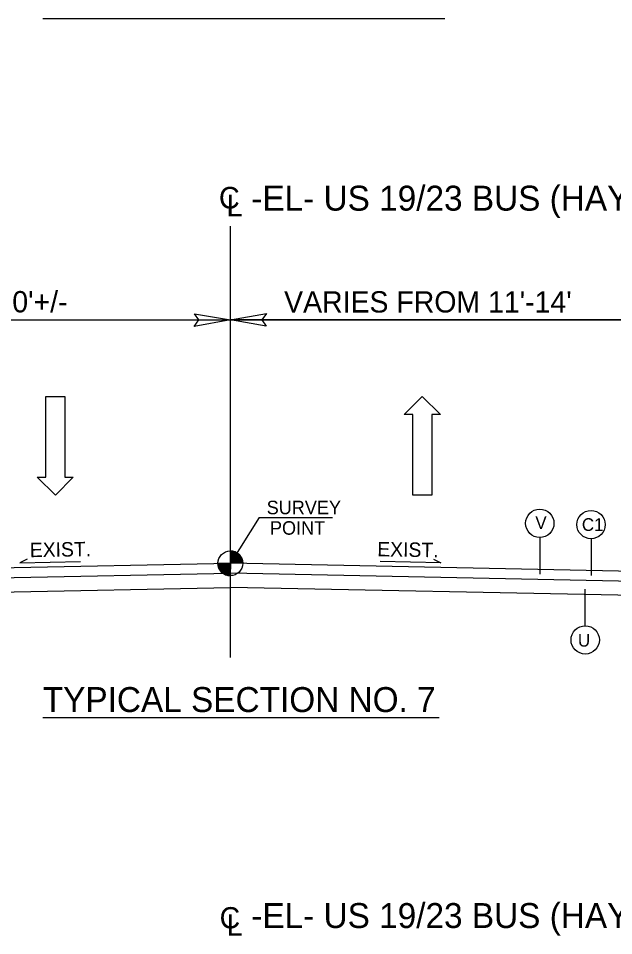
# Model space of a CAD drawing. Extents: x 1022283 to 1026986, y 174822 to 180471.
# Drawn here: x 1023671 to 1024119, y 176179 to 176868 of the extents above; entities that cross this region are included whole.
import ezdxf

# ---------------------------------------------------------------- set-up
doc = ezdxf.new("R2010")
doc.units = 0
for name, color, linetype in [('Default', 7, 'Continuous'), ('Prop Dimension', 7, 'Continuous'), ('Prop Lane Arrow CELL', 7, 'Continuous'), ('Prop Terminator CELL', 7, 'Continuous'), ('Typical Berm Information CELL', 7, 'Continuous'), ('Typical Grade Point Symbol CELL', 7, 'Continuous'), ('Typical ID Circle CELL', 7, 'Continuous'), ('Typical Text Centerline CELL', 7, 'Continuous'), ('Typical Text Grade Point CELL', 7, 'Continuous'), ('Typical Text ID Circle CELL', 7, 'Continuous'), ('Typical Text Label CELL', 7, 'Continuous')]:
    doc.layers.add(name, color=color, linetype=linetype)

# ---------------------------------------------------------------- blocks, each defined once
blk = doc.blocks.new('Lane Arrow Through')
at = {"layer": 'Prop Lane Arrow CELL'}
for p, q in [((-17.15, 1.6), (-3.15, 1.6)), ((-17.15, -1.7), (-17.15, 1.6)), ((-3.15, 1.6), (-3.15, 3.1)), ((-3.15, 3.1), (0, 0)), ((0, 0), (-3.15, -3.2)), ((-3.15, -1.7), (-17.15, -1.7)), ((-3.15, -3.2), (-3.15, -1.7))]:
    blk.add_line(p, q, dxfattribs=at)

msp = doc.modelspace()

# ---------------------------------------------------------------- linework, layer by layer
at = {"layer": 'Default'}
for p, q in [((1023322.83, 176641.78), (1023830.54, 176641.78)), ((1023830.54, 176641.78), (1024338.25, 176641.78)), ((1024338.25, 176641.78), (1023830.54, 176641.78))]:
    msp.add_line(p, q, dxfattribs=at)
at = {"layer": 'Prop Dimension'}
for p, q in [((1023830.54, 176652.9), (1023830.54, 176712.35)), ((1023830.54, 176388.1), (1023830.54, 176652.9)), ((1023852.19, 176493.32), (1023830.54, 176458.89)), ((1023852.19, 176493.32), (1023830.54, 176458.89)), ((1023322.83, 176448.73), (1023830.54, 176458.89)), ((1023322.83, 176448.73), (1023830.54, 176458.89)), ((1024338.25, 176448.73), (1023830.54, 176458.89)), ((1024338.25, 176448.73), (1023830.54, 176458.89)), ((1023322.83, 176441.23), (1023830.54, 176451.38)), ((1023322.83, 176441.23), (1023830.54, 176451.38)), ((1024338.25, 176441.23), (1023830.54, 176451.38)), ((1024338.25, 176441.23), (1023830.54, 176451.38)), ((1023322.83, 176430.65), (1023830.54, 176440.8)), ((1024338.25, 176430.65), (1023830.54, 176440.8))]:
    msp.add_line(p, q, dxfattribs=at)
at = {"layer": 'Prop Terminator CELL'}
for points in [[(1023803.54, 176646.43), (1023830.54, 176641.78), (1023803.39, 176636.98), (1023806.84, 176641.78)], [(1023857.54, 176637.13), (1023830.54, 176641.78), (1023857.69, 176646.58), (1023854.24, 176641.78)], [(1023857.54, 176637.13), (1023830.54, 176641.78), (1023857.69, 176646.58), (1023854.24, 176641.78)]]:
    msp.add_lwpolyline(points, close=True, dxfattribs=at)
at = {"layer": 'Typical Berm Information CELL'}
for p, q in [((1023677.89, 176462.1), (1023672.37, 176459.33)), ((1023672.37, 176459.33), (1023717.88, 176460.24)), ((1023988.71, 176459.33), (1023943.2, 176460.24)), ((1023983.19, 176462.1), (1023988.71, 176459.33))]:
    msp.add_line(p, q, dxfattribs=at)
at = {"layer": 'Typical Grade Point Symbol CELL'}
for p, q in [((1023830.54, 176458.89), (1023830.54, 176468.18)), ((1023830.54, 176458.89), (1023830.54, 176468.18)), ((1023821.24, 176458.89), (1023830.54, 176458.89)), ((1023821.24, 176458.89), (1023830.54, 176458.89)), ((1023830.52, 176449.59), (1023830.54, 176458.89)), ((1023830.54, 176458.89), (1023830.52, 176449.59)), ((1023830.52, 176449.59), (1023830.54, 176458.89)), ((1023830.54, 176458.89), (1023830.52, 176449.59)), ((1023839.83, 176458.89), (1023830.54, 176458.89)), ((1023839.83, 176458.89), (1023830.54, 176458.89))]:
    msp.add_line(p, q, dxfattribs=at)
for points in [[(1023830.62, 176468.18), (1023830.62, 176468.18), (1023830.62, 176458.89)], [(1023830.62, 176468.18), (1023830.62, 176468.18), (1023830.62, 176458.89)], [(1023830.81, 176468.18), (1023830.81, 176458.89)], [(1023830.81, 176468.18), (1023830.81, 176458.89)], [(1023830.99, 176468.16), (1023830.99, 176458.89)], [(1023830.99, 176468.16), (1023830.99, 176458.89)], [(1023831.18, 176468.16), (1023831.18, 176458.89)], [(1023831.18, 176468.16), (1023831.18, 176458.89)], [(1023831.37, 176468.14), (1023831.37, 176458.89)], [(1023831.37, 176468.14), (1023831.37, 176458.89)], [(1023831.55, 176468.12), (1023831.55, 176458.89)], [(1023831.55, 176468.12), (1023831.55, 176458.89)], [(1023831.74, 176468.1), (1023831.74, 176458.89)], [(1023831.74, 176468.1), (1023831.74, 176458.89)], [(1023831.92, 176468.08), (1023831.92, 176458.89)], [(1023831.92, 176468.08), (1023831.92, 176458.89)], [(1023832.11, 176468.06), (1023832.11, 176458.89)], [(1023832.11, 176468.06), (1023832.11, 176458.89)], [(1023832.3, 176468.02), (1023832.3, 176458.89)], [(1023832.3, 176468.02), (1023832.3, 176458.89)], [(1023832.48, 176467.98), (1023832.48, 176458.89)], [(1023832.48, 176467.98), (1023832.48, 176458.89)], [(1023832.67, 176467.93), (1023832.67, 176458.89)], [(1023832.67, 176467.93), (1023832.67, 176458.89)], [(1023832.85, 176467.89), (1023832.85, 176458.89)], [(1023832.85, 176467.89), (1023832.85, 176458.89)], [(1023833.04, 176467.83), (1023833.04, 176458.89)], [(1023833.04, 176467.83), (1023833.04, 176458.89)], [(1023833.22, 176467.79), (1023833.22, 176458.89)], [(1023833.22, 176467.79), (1023833.22, 176458.89)], [(1023833.41, 176467.73), (1023833.41, 176458.89)], [(1023833.41, 176467.73), (1023833.41, 176458.89)], [(1023833.6, 176467.67), (1023833.6, 176458.89)], [(1023833.6, 176467.67), (1023833.6, 176458.89)], [(1023833.78, 176467.6), (1023833.78, 176458.89)], [(1023833.78, 176467.6), (1023833.78, 176458.89)], [(1023833.97, 176467.52), (1023833.97, 176458.89)], [(1023833.97, 176467.52), (1023833.97, 176458.89)], [(1023834.15, 176467.44), (1023834.15, 176458.89)], [(1023834.15, 176467.44), (1023834.15, 176458.89)], [(1023834.34, 176467.36), (1023834.34, 176458.89)], [(1023834.34, 176467.36), (1023834.34, 176458.89)], [(1023834.53, 176467.27), (1023834.53, 176458.89)], [(1023834.53, 176467.27), (1023834.53, 176458.89)], [(1023834.71, 176467.19), (1023834.71, 176458.89)], [(1023834.71, 176467.19), (1023834.71, 176458.89)], [(1023834.9, 176467.09), (1023834.9, 176458.89)], [(1023834.9, 176467.09), (1023834.9, 176458.89)], [(1023835.08, 176466.98), (1023835.08, 176458.89)], [(1023835.08, 176466.98), (1023835.08, 176458.89)], [(1023835.27, 176466.88), (1023835.27, 176458.89)], [(1023835.27, 176466.88), (1023835.27, 176458.89)], [(1023835.46, 176466.78), (1023835.46, 176458.89)], [(1023835.46, 176466.78), (1023835.46, 176458.89)], [(1023835.64, 176466.65), (1023835.64, 176458.89)], [(1023835.64, 176466.65), (1023835.64, 176458.89)], [(1023835.83, 176466.53), (1023835.83, 176458.89)], [(1023835.83, 176466.53), (1023835.83, 176458.89)], [(1023836.01, 176466.39), (1023836.01, 176458.89)], [(1023836.01, 176466.39), (1023836.01, 176458.89)], [(1023836.2, 176466.26), (1023836.2, 176458.89)], [(1023836.2, 176466.26), (1023836.2, 176458.89)], [(1023836.39, 176466.12), (1023836.39, 176458.89)], [(1023836.39, 176466.12), (1023836.39, 176458.89)], [(1023836.57, 176465.95), (1023836.57, 176458.89)], [(1023836.57, 176465.95), (1023836.57, 176458.89)], [(1023836.76, 176465.79), (1023836.76, 176458.89)], [(1023836.76, 176465.79), (1023836.76, 176458.89)], [(1023836.94, 176465.62), (1023836.94, 176458.89)], [(1023836.94, 176465.62), (1023836.94, 176458.89)], [(1023837.13, 176465.43), (1023837.13, 176458.89)], [(1023837.13, 176465.43), (1023837.13, 176458.89)], [(1023837.32, 176465.25), (1023837.32, 176458.89)], [(1023837.32, 176465.25), (1023837.32, 176458.89)], [(1023837.5, 176465.04), (1023837.5, 176458.89)], [(1023837.5, 176465.04), (1023837.5, 176458.89)], [(1023837.69, 176464.82), (1023837.69, 176458.89)], [(1023837.69, 176464.82), (1023837.69, 176458.89)], [(1023837.87, 176464.59), (1023837.87, 176458.89)], [(1023837.87, 176464.59), (1023837.87, 176458.89)], [(1023838.06, 176464.34), (1023838.06, 176458.89)], [(1023838.06, 176464.34), (1023838.06, 176458.89)], [(1023838.25, 176464.07), (1023838.25, 176458.89)], [(1023838.25, 176464.07), (1023838.25, 176458.89)], [(1023838.43, 176463.78), (1023838.43, 176458.89)], [(1023838.43, 176463.78), (1023838.43, 176458.89)], [(1023838.62, 176463.47), (1023838.62, 176458.89)], [(1023838.62, 176463.47), (1023838.62, 176458.89)], [(1023838.8, 176463.14), (1023838.8, 176458.89)], [(1023838.8, 176463.14), (1023838.8, 176458.89)], [(1023838.99, 176462.75), (1023838.99, 176458.89)], [(1023838.99, 176462.75), (1023838.99, 176458.89)], [(1023839.17, 176462.32), (1023839.17, 176458.89)], [(1023839.17, 176462.32), (1023839.17, 176458.89)], [(1023839.36, 176461.8), (1023839.36, 176458.89)], [(1023839.36, 176461.8), (1023839.36, 176458.89)], [(1023839.55, 176461.16), (1023839.55, 176458.89)], [(1023839.55, 176461.16), (1023839.55, 176458.89)], [(1023839.73, 176460.21), (1023839.73, 176458.89)], [(1023839.73, 176460.21), (1023839.73, 176458.89)], [(1023821.29, 176458.89), (1023821.29, 176457.87)], [(1023821.29, 176458.89), (1023821.29, 176457.87)], [(1023821.47, 176458.89), (1023821.47, 176456.78)], [(1023821.47, 176458.89), (1023821.47, 176456.78)], [(1023821.66, 176458.89), (1023821.66, 176456.12)], [(1023821.66, 176458.89), (1023821.66, 176456.12)], [(1023821.84, 176458.89), (1023821.84, 176455.56)], [(1023821.84, 176458.89), (1023821.84, 176455.56)], [(1023822.03, 176458.89), (1023822.03, 176455.13)], [(1023822.03, 176458.89), (1023822.03, 176455.13)], [(1023822.22, 176458.89), (1023822.22, 176454.73)], [(1023822.22, 176458.89), (1023822.22, 176454.73)], [(1023822.4, 176458.89), (1023822.4, 176454.38)], [(1023822.4, 176458.89), (1023822.4, 176454.38)], [(1023822.59, 176458.89), (1023822.59, 176454.05)], [(1023822.59, 176458.89), (1023822.59, 176454.05)], [(1023822.77, 176458.89), (1023822.77, 176453.76)], [(1023822.77, 176458.89), (1023822.77, 176453.76)], [(1023822.96, 176458.89), (1023822.96, 176453.5)], [(1023822.96, 176458.89), (1023822.96, 176453.5)], [(1023823.15, 176458.89), (1023823.15, 176453.25)], [(1023823.15, 176458.89), (1023823.15, 176453.25)], [(1023823.33, 176458.89), (1023823.33, 176453.02)], [(1023823.33, 176458.89), (1023823.33, 176453.02)], [(1023823.52, 176458.89), (1023823.52, 176452.79)], [(1023823.52, 176458.89), (1023823.52, 176452.79)], [(1023823.7, 176458.89), (1023823.7, 176452.59)], [(1023823.7, 176458.89), (1023823.7, 176452.59)], [(1023823.89, 176458.89), (1023823.89, 176452.38)], [(1023823.89, 176458.89), (1023823.89, 176452.38)], [(1023824.07, 176458.89), (1023824.07, 176452.19)], [(1023824.07, 176458.89), (1023824.07, 176452.19)], [(1023824.26, 176458.89), (1023824.26, 176452.03)], [(1023824.26, 176458.89), (1023824.26, 176452.03)], [(1023824.45, 176458.89), (1023824.45, 176451.86)], [(1023824.45, 176458.89), (1023824.45, 176451.86)], [(1023824.63, 176458.89), (1023824.63, 176451.7)], [(1023824.63, 176458.89), (1023824.63, 176451.7)], [(1023824.82, 176458.89), (1023824.82, 176451.55)], [(1023824.82, 176458.89), (1023824.82, 176451.55)], [(1023825, 176458.89), (1023825, 176451.41)], [(1023825, 176458.89), (1023825, 176451.41)], [(1023825.19, 176458.89), (1023825.19, 176451.29)], [(1023825.19, 176458.89), (1023825.19, 176451.29)], [(1023825.38, 176458.89), (1023825.38, 176451.16)], [(1023825.38, 176458.89), (1023825.38, 176451.16)], [(1023825.56, 176458.89), (1023825.56, 176451.04)], [(1023825.56, 176458.89), (1023825.56, 176451.04)], [(1023825.75, 176458.89), (1023825.75, 176450.91)], [(1023825.75, 176458.89), (1023825.75, 176450.91)], [(1023825.93, 176458.89), (1023825.93, 176450.81)], [(1023825.93, 176458.89), (1023825.93, 176450.81)], [(1023826.12, 176458.89), (1023826.12, 176450.71)], [(1023826.12, 176458.89), (1023826.12, 176450.71)], [(1023826.31, 176458.89), (1023826.31, 176450.6)], [(1023826.31, 176458.89), (1023826.31, 176450.6)], [(1023826.49, 176458.89), (1023826.49, 176450.52)], [(1023826.49, 176458.89), (1023826.49, 176450.52)], [(1023826.68, 176458.89), (1023826.68, 176450.44)], [(1023826.68, 176458.89), (1023826.68, 176450.44)], [(1023826.86, 176458.89), (1023826.86, 176450.36)], [(1023826.86, 176458.89), (1023826.86, 176450.36)], [(1023827.05, 176458.89), (1023827.05, 176450.27)], [(1023827.05, 176458.89), (1023827.05, 176450.27)], [(1023827.23, 176458.89), (1023827.23, 176450.19)], [(1023827.23, 176458.89), (1023827.23, 176450.19)], [(1023827.42, 176458.89), (1023827.42, 176450.13)], [(1023827.42, 176458.89), (1023827.42, 176450.13)], [(1023827.61, 176458.89), (1023827.61, 176450.07)], [(1023827.61, 176458.89), (1023827.61, 176450.07)], [(1023827.79, 176458.89), (1023827.79, 176450)], [(1023827.79, 176458.89), (1023827.79, 176450)], [(1023827.98, 176458.89), (1023827.98, 176449.96)], [(1023827.98, 176458.89), (1023827.98, 176449.96)], [(1023828.16, 176458.89), (1023828.16, 176449.9)], [(1023828.16, 176458.89), (1023828.16, 176449.9)], [(1023828.35, 176458.89), (1023828.35, 176449.86)], [(1023828.35, 176458.89), (1023828.35, 176449.86)], [(1023828.54, 176458.89), (1023828.54, 176449.82)], [(1023828.54, 176458.89), (1023828.54, 176449.82)], [(1023828.72, 176458.89), (1023828.72, 176449.78)], [(1023828.72, 176458.89), (1023828.72, 176449.78)], [(1023828.91, 176458.89), (1023828.91, 176449.74)], [(1023828.91, 176458.89), (1023828.91, 176449.74)], [(1023829.09, 176458.89), (1023829.09, 176449.72)], [(1023829.09, 176458.89), (1023829.09, 176449.72)], [(1023829.28, 176458.89), (1023829.28, 176449.67)], [(1023829.28, 176458.89), (1023829.28, 176449.67)], [(1023829.47, 176458.89), (1023829.47, 176449.65)], [(1023829.47, 176458.89), (1023829.47, 176449.65)], [(1023829.65, 176458.89), (1023829.65, 176449.63)], [(1023829.65, 176458.89), (1023829.65, 176449.63)], [(1023829.84, 176458.89), (1023829.84, 176449.61)], [(1023829.84, 176458.89), (1023829.84, 176449.61)], [(1023830.02, 176458.89), (1023830.02, 176449.61)], [(1023830.02, 176458.89), (1023830.02, 176449.61)], [(1023830.21, 176458.89), (1023830.21, 176449.59)], [(1023830.21, 176458.89), (1023830.21, 176449.59)], [(1023830.4, 176458.89), (1023830.4, 176449.59), (1023830.4, 176449.59)], [(1023830.4, 176458.89), (1023830.4, 176449.59), (1023830.4, 176449.59)]]:
    msp.add_lwpolyline(points, dxfattribs=at)
msp.add_circle((1023830.53, 176458.89), 9.3, dxfattribs=at)
msp.add_circle((1023830.53, 176458.89), 9.3, dxfattribs=at)
for start, end in [(359.99048, 89.99048), (359.99048, 89.99048), (179.99048, 269.99048), (179.99048, 269.99048)]:
    msp.add_arc((1023830.53, 176458.89), 9.3, start, end, dxfattribs=at)
at = {"layer": 'Typical ID Circle CELL'}
for p, q in [((1024063.18, 176478.28), (1024063.18, 176450.75)), ((1024101.71, 176477.32), (1024101.71, 176449.79)), ((1024097.31, 176411.95), (1024097.31, 176439.48))]:
    msp.add_line(p, q, dxfattribs=at)
for centre in [(1024063.18, 176488.93), (1024101.71, 176487.97), (1024097.31, 176401.31)]:
    msp.add_circle(centre, 10.65, dxfattribs=at)
at = {"layer": 'Typical Text Grade Point CELL'}
msp.add_line((1023852.19, 176493.32), (1023907.29, 176493.32), dxfattribs=at)
at = {"layer": 'Typical Text Label CELL'}
for p, q in [((1023689.52, 176868.49), (1023991.9, 176868.49)), ((1023689.52, 176343.08), (1023987.51, 176343.08))]:
    msp.add_line(p, q, dxfattribs=at)

# ---------------------------------------------------------------- block references
at = {"layer": 'Prop Lane Arrow CELL', "xscale": 4.329849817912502}
for p, yscale, rotation in [((1023699.06, 176510.09), 4.3298498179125, -89.99999999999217), ((1023974.73, 176584.35), 4.329849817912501, 90.00000000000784), ((1023974.73, 176584.35), 4.329849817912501, 90.00000000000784)]:
    msp.add_blockref('Lane Arrow Through', p, dxfattribs=dict(at, yscale=yscale, rotation=rotation))

# ---------------------------------------------------------------- texts
at = {"layer": 'Prop Dimension'}
for s, height, p in [('-EL- US 19/23 BUS (HAYWOOD RD) ', 18.75, (1023846.26, 176723.95)), ("10'+/-", 16, (1023654.69, 176647.5)), ("VARIES FROM 11'-14'", 16, (1023870.94, 176647.38)), ('-EL- US 19/23 BUS (HAYWOOD RD) ', 18.75, (1023846.26, 176184.74))]:
    msp.add_text(s, height=height, dxfattribs=at).set_placement(p)
at = {"layer": 'Typical Berm Information CELL'}
for rotation, p in [(0.99274, (1023679.85, 176463.44)), (359.00726, (1023940.94, 176464.14))]:
    msp.add_text('EXIST.', height=10.873, rotation=rotation, dxfattribs=at).set_placement(p)
at = {"layer": 'Typical Text Centerline CELL'}
for height, p in [(16.22, (1023821.95, 176725.55)), (15.97, (1023822.49, 176184.47))]:
    msp.add_text('C', height=height, dxfattribs=at).set_placement(p)
for height, p in [(16.22, (1023827.61, 176719.74)), (15.98, (1023827.8, 176179.01))]:
    msp.add_text('L', height=height, rotation=359.9469, dxfattribs=at).set_placement(p)
at = {"layer": 'Typical Text Grade Point CELL'}
for s, p in [('SURVEY', (1023857.85, 176495.76)), ('POINT', (1023860.3, 176480.36))]:
    msp.add_text(s, height=10.163, dxfattribs=at).set_placement(p)
at = {"layer": 'Typical Text ID Circle CELL'}
for s, height, p in [('V', 9.53, (1024059.83, 176484.63)), ('C1', 9.534, (1024094.82, 176483.24)), ('U', 9.53, (1024091.86, 176396.24))]:
    msp.add_text(s, height=height, dxfattribs=at).set_placement(p)
at = {"layer": 'Typical Text Label CELL'}
msp.add_text('TYPICAL SECTION NO. 7', height=18.75, dxfattribs=at).set_placement((1023689.52, 176347.08))

doc.saveas('drawing.dxf')
